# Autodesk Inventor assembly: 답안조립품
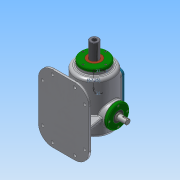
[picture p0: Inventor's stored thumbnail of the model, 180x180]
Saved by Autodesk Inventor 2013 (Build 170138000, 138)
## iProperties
Created: 2019-10
Part Number: 답안조립품
Document SubType Name: Assembly
Designer: Administrator
Author: Administrator
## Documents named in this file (17)
- C:\Users\Administrator\Desktop\391004V1013\답안조립품.iam
- C:\Users\Administrator\Desktop\391004V1013\본체.ipt
- C:\Users\Administrator\Desktop\391004V1013\가변스프링.ipt
- C:\Users\Administrator\Desktop\391004V1013\개스킷 A.ipt
- C:\Users\Administrator\Desktop\391004V1013\개스킷 B.ipt
- C:\Users\Administrator\Desktop\391004V1013\고정플레이트.ipt
- C:\Users\Administrator\Desktop\391004V1013\베어링 6205.ipt
- 베어링 6205.ipt
- C:\Users\Administrator\Desktop\391004V1013\볼트 M4x0.7.ipt
- C:\Users\Administrator\Desktop\391004V1013\부시.ipt
- C:\Users\Administrator\Desktop\391004V1013\상부커버.ipt
- C:\Users\Administrator\Desktop\391004V1013\슬라이드 커버.ipt
- C:\Users\Administrator\Desktop\391004V1013\슬라이드.ipt
- C:\Users\Administrator\Desktop\391004V1013\오일 실 25 38 8.ipt
- C:\Users\Administrator\Desktop\391004V1013\육각머리볼트 M4.ipt
- C:\Users\Administrator\Desktop\391004V1013\축 커버.ipt
- C:\Users\Administrator\Desktop\391004V1013\편심축.ipt
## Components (17 placed, 5 different names)
1. 가변스프링:1
2. 개스킷 A:1
3. 개스킷 B:1
4. 고정플레이트:1 — 플러쉬:1
5. 개스킷 B:2
6. M4x0.7:1
7. M4x0.7:4
8. M4x0.7:5
9. M4x0.7:6
10. M4x0.7:2
11. M4x0.7:7
12. M4x0.7:8
13. M4x0.7:9
14. M4x0.7:3
15. M4x0.7:10
16. M4x0.7:11
17. M4x0.7:12
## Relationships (1: Flush 1)
- 플러쉬:1 [Flush]: 고정플레이트:1
